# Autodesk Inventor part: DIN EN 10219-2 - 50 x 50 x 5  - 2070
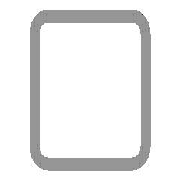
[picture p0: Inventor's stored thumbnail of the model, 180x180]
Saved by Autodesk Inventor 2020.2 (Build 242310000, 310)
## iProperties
Created: 2019-01
Part Number: DIN EN 10219-2 - 50 x 50 x 5  - 2070
Material: Stahl, weich
Description: Kaltgeformte, geschweißte Baustahl-Hohlprofile aus unlegiertem Feinkorn-Baustahl
Document SubType Name: Modeling
Standard: DIN
Designer: lutzd
Standard Revision: 2006-07
Standards Organization: DIN
Language: de-DE
Size Designation: 50 x 50 x 5
Categories: <MemberInstance><Categories><Category DisplayName="Profile" InternalName="089c4875-fa83-4c05-b084-43b9cc11f5ed" Mnemonic="GRDR"><CategoryParameter DisplayName="
Stock Number: 50 x 50 x 5
Mass: 13576.3 g
Surface Area: 6937.17 cm^2
Volume: 1729.46 cm^3
Density: 7.85 g/cm^3
Appearance: Semi-Polished(8)
IsCustomPart: 1
G_L: 2070,000 mm
G_W: 50,000 mm
G_H: 50,000 mm
DocNumber: ADSK-014376
Folder: .
Mass: 13,576 kg
VLT_Material: Stahl, weich
+43EC5CA1-AD5E-4862-8586-44250B267498+SCHNITTDETAIL1: Schnittwinkel 90,00 grd
Dimensions: 50x50x2070 mm
+7412A6F4-F3AF-4281-BB6A-B591CFC42B3C+SCHNITTDETAIL2: Schnittwinkel 90,00 grd
_CCFamilyMember: 16
_CCFamilyDisplayName: DIN EN 10219-2 (Quadratisches Hohlprofil - Kaltgeformt) - Kaltgeformte, geschweißte Baustahl-Hohlprofile aus unlegiertem Feinkorn-Baustahl
_FrameMemberDoc: Frame Member File
_Version: 15.0.0
_GetPNFromCC: 1
Title: Profil-Bauteil
Author: lutzd
Revision Number: -
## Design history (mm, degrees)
node "Startebene"
node "Endebene"
sketch "Skizze"
  geometry: L1 (-25, -15)-(-25, 15); L2 (-15, 25)-(15, 25); L3 (25, 15)-(25, -15); L4 (15, -25)-(-15, -25); L5 (-15, 20)-(15, 20); L6 (20, 15)-(20, -15); L7 (15, -20)-(-15, -20); L8 (-20, -15)-(-20, 15); L9 (0, 37.899)-(0, -37.899) reference; L10 (-37.899, 0)-(37.899, 0) reference; A1 r 10 centre (-15, -15) between (-25, -15) and (-15, -25); A2 r 10 centre (-15, 15) between (-15, 25) and (-25, 15); A3 r 10 centre (15, 15) between (25, 15) and (15, 25); A4 r 10 centre (15, -15) between (15, -25) and (25, -15); A5 r 5 centre (-15, 15) between (-15, 20) and (-20, 15); A6 r 5 centre (15, 15) between (20, 15) and (15, 20); A7 r 5 centre (15, -15) between (15, -20) and (20, -15); A8 r 5 centre (-15, -15) between (-20, -15) and (-15, -20)
  constraints: 16 end point, 16 point on circle, 8 centre point, 8 tangent, 4 parallel, 3 equal radius, 2 perpendicular, 7 other
  dimensions: "d7" = 10 radius of A1 (= G_IR); "d10" = 50 distance between parallel lines of L2 L4 (= G_H); "d11" = 50 distance between parallel lines of L1 L3 (= G_W); "d12" = 5 distance between parallel lines of L3 L6 (= G_T); "d15" = 25 distance between parallel lines of L2 L10 (= 0.5 x d10); "d16" = 25 distance between parallel lines of L9 L3 (= 0.5 x d11)
extrude "Körper" new body sketch "Skizze" stored distance "d3" = 2070 (= G_L); taper "d4" = 0 deg
node "Driven Length"
  sketch "Sketch3"
    geometry: L1 (0, 0)-(10, 0) reference
    constraints: 2 end point, 1 horizontal
  workplane "Work Plane3"
  sketch "Sketch4"
    geometry: L1 (-2, 50)-(12, 50) reference; L2 (-2, 2120)-(12, 2120) reference
    dimensions: "d18" = 2070 distance between parallel lines of L1 L2 (derived)
workplane "Arbeitsebene4"
feature "Trennen1"
workplane "Arbeitsebene5"
feature "Trennen2"
sketch "Skizze5"
  geometry: L1 (-30, 2070)-(0, 2070) reference; L2 (-15, 2070)-(-15, 1739); L3 (-30, 0)-(0, 0) reference; L4 (-15, 0)-(-15, 331); 5 further points
  constraints: 4 end point, 2 coincident, 2 midpoint, 2 point on line, 2 vertical
  dimensions: "d19" = 331 distance of L2.start L2.end; "d20" = 281 distance of L2.end point (-15, 2020); "d28" = 331 distance of L4.start L4.end (= d19); "d29" = 281 distance of point (-15, 331) point (-15, 50) (= d20)
hole "Bohrung1" sketch "Skizze5" at (-15, 2020), (-15, 1739), (-15, 50), (-15, 331) diameter "d21" = 4.134; stored, may be unused: countersink angle "d25" = 90 deg, drill point angle "d27" = 118 deg; dims "d22" = 10, "d23" = 4, "d24" = 2, "d26" = 8
body "Solid1"
other parameters: "G_W" = 50 [user parameter; used in 1 equation term], "G_H" = 50 [user parameter; used in 1 equation term], "G_T" = 5 [user parameter; used in 1 equation term], "G_IR" = 10 [user parameter; used in 1 equation term], "G_L" = 2070 (= d18) [user parameter; used in 1 equation term], "d17" = 90 deg
